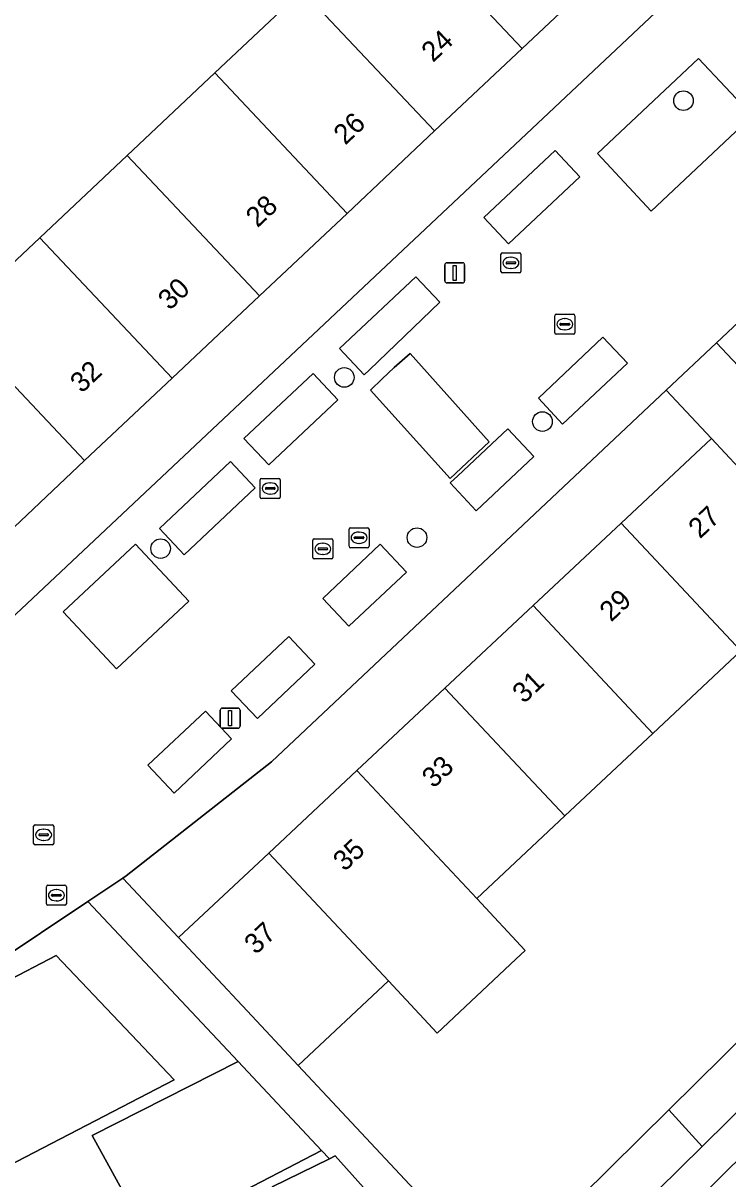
# Model space of a CAD drawing. Extents: x 161881 to 162523, y 381678 to 382381.
# Drawn here: x 162341.8 to 162377, y 381766.4 to 381824.1 of the extents above; entities that cross this region are included whole.
import ezdxf

# ---------------------------------------------------------------- set-up
doc = ezdxf.new("R2010")
doc.units = 0
for name, color, linetype in [('IMGEO_Boom', 7, 'Continuous'), ('IMGEO_Brandkraan', 7, 'Continuous'), ('IMGEO_Erf', 7, 'Continuous'), ('IMGEO_Groenvoorziening', 7, 'Continuous'), ('IMGEO_Kolk', 7, 'Continuous'), ('IMGEO_Lichtmast', 7, 'Continuous'), ('IMGEO_Pand', 7, 'Continuous'), ('IMGEO_Pand_nummerreeks', 7, 'Continuous'), ('IMGEO_Parkeervlak_open', 7, 'Continuous'), ('IMGEO_Rijbaan_lokaal_open', 7, 'Continuous'), ('IMGEO_Rioolput', 7, 'Continuous'), ('IMGEO_Voetpad_open', 7, 'Continuous')]:
    doc.layers.add(name, color=color, linetype=linetype)

msp = doc.modelspace()

# ---------------------------------------------------------------- linework, layer by layer
at = {"layer": 'IMGEO_Boom'}
for centre in [(162374.75, 381820.189), (162357.829, 381806.387), (162367.715, 381804.185), (162361.458, 381798.398), (162348.668, 381797.849)]:
    msp.add_circle(centre, 0.489, dxfattribs=at)
at = {"layer": 'IMGEO_Brandkraan'}
for p, q in [((162342.967, 381780.137), (162342.967, 381780.989)), ((162343.042, 381781.063), (162343.894, 381781.063)), ((162343.455, 381780.843), (162343.48, 381780.843)), ((162343.968, 381780.989), (162343.968, 381780.137)), ((162343.226, 381780.557), (162343.226, 381780.569)), ((162343.664, 381780.52), (162343.266, 381780.52)), ((162343.269, 381780.606), (162343.667, 381780.606)), ((162343.478, 381780.283), (162343.453, 381780.283)), ((162343.71, 381780.569), (162343.71, 381780.557)), ((162343.894, 381780.063), (162343.042, 381780.063))]:
    msp.add_line(p, q, dxfattribs=at)
for points in [[(162342.967, 381780.137), (162342.967, 381780.989)], [(162343.042, 381781.063), (162343.894, 381781.063)], [(162343.968, 381780.989), (162343.968, 381780.137)], [(162343.894, 381780.063), (162343.042, 381780.063)]]:
    msp.add_lwpolyline(points, dxfattribs=at)
for centre, radius, start, end in [((162343.044, 381780.987), 0.0765, 91.55205, 178.44795), ((162343.044, 381780.987), 0.0765, 91.55205, 178.44795), ((162343.892, 381780.987), 0.0765, 1.55205, 88.44795), ((162343.892, 381780.987), 0.0765, 1.55205, 88.44795), ((162343.266, 381780.566), 0.0403, 85.87752, 175.75265), ((162343.263, 381780.556), 0.0366, 178.93798, 274.71019), ((162343.667, 381780.563), 0.043, 264.86636, 352.45326), ((162343.671, 381780.568), 0.0386, 1.73085, 96.63898), ((162343.044, 381780.139), 0.0765, 181.55205, 268.44795), ((162343.044, 381780.139), 0.0765, 181.55205, 268.44795), ((162343.892, 381780.139), 0.0765, 271.55205, 358.44795), ((162343.892, 381780.139), 0.0765, 271.55205, 358.44795)]:
    msp.add_arc(centre, radius, start, end, dxfattribs=at)
for centre, major_axis, ratio, start_param, end_param in [((162343.454, 381780.563), (-0.387, 0.002), 0.722429, 4.712389, 7.853982), ((162343.479, 381780.563), (-0.39, 0.002), 0.717154, 1.570796, 4.712389)]:
    msp.add_ellipse(centre, major_axis=major_axis, ratio=ratio, start_param=start_param, end_param=end_param, dxfattribs=at)
at = {"layer": 'IMGEO_Erf'}
for points in [[(162414.428, 381843.9), (162376.404, 381808.113), (162383.389, 381800.691)], [(162332.07, 381824.564), (162327.383, 381820.796), (162319.893, 381814.774), (162328.853, 381805.184), (162331.62, 381807.79), (162334.025, 381805.238), (162338.274, 381809.24), (162342.639, 381813.35), (162347.004, 381817.46), (162351.368, 381821.57), (162355.733, 381825.68)], [(162369.629, 381765.527), (162374.022, 381769.859), (162378.082, 381773.863), (162382.473, 381778.193), (162386.785, 381782.445), (162390.429, 381786.038), (162389.849, 381786.627), (162387.914, 381788.589), (162389.897, 381790.545), (162394.14, 381786.241), (162394.352, 381786.45), (162385.347, 381796.033), (162382.932, 381796.092), (162382.12, 381796.96), (162377.619, 381792.746), (162373.224, 381788.631), (162368.83, 381784.517), (162364.435, 381780.403), (162366.852, 381777.807), (162366.391, 381777.376), (162362.458, 381773.692), (162360.041, 381776.288), (162355.536, 381772.071), (162363.995, 381763.033)], [(162354.236, 381766.022), (162357.084, 381767.419), (162356.7, 381767.828), (162348.117, 381763.384), (162345.256, 381768.578), (162352.533, 381772.272), (162345.044, 381780.258), (162340.347, 381777.133), (162340.852, 381776.203), (162343.461, 381777.564), (162346.9, 381773.934), (162349.34, 381771.36), (162327.927, 381760.251)], [(162381.418, 381771.264), (162367.187, 381757.231)]]:
    msp.add_lwpolyline(points, dxfattribs=at)
for points in [[(162377.552, 381828.547), (162383.149, 381833.811), (162380.574, 381836.724), (162378.448, 381836.809), (162374.061, 381832.677), (162375.536, 381831.111), (162371.061, 381826.897), (162366.697, 381822.787), (162362.333, 381818.677), (162357.968, 381814.567), (162353.605, 381810.457), (162349.24, 381806.347), (162344.875, 381802.236), (162340.402, 381798.024), (162340.265, 381798.17), (162339.511, 381798.971), (162336.964, 381796.572), (162337.718, 381795.771), (162340.037, 381793.265)], [(162367.248, 381795.01), (162371.642, 381799.125), (162376.146, 381803.341), (162373.886, 381805.743), (162354.206, 381787.221), (162346.948, 381781.525), (162346.786, 381781.417), (162349.562, 381778.452), (162354.064, 381782.667), (162358.459, 381786.781), (162362.853, 381790.895)]]:
    msp.add_lwpolyline(points, close=True, dxfattribs=at)
at = {"layer": 'IMGEO_Groenvoorziening'}
for points in [[(162373.145, 381814.683), (162378.194, 381819.432), (162375.501, 381822.295), (162370.453, 381817.546)], [(162346.471, 381791.847), (162350.082, 381795.233), (162347.414, 381798.078), (162343.803, 381794.692)]]:
    msp.add_lwpolyline(points, close=True, dxfattribs=at)
at = {"layer": 'IMGEO_Kolk'}
for p, q in [((162365.717, 381812.601), (162366.569, 381812.601)), ((162365.642, 381811.675), (162365.642, 381812.527)), ((162365.901, 381812.095), (162365.901, 381812.107)), ((162366.339, 381812.058), (162365.941, 381812.058)), ((162365.944, 381812.144), (162366.342, 381812.144)), ((162366.13, 381812.381), (162366.155, 381812.381)), ((162366.385, 381812.107), (162366.385, 381812.095)), ((162366.643, 381812.527), (162366.643, 381811.675)), ((162366.569, 381811.601), (162365.717, 381811.601)), ((162366.153, 381811.821), (162366.128, 381811.821)), ((162368.33, 381808.614), (162368.33, 381809.466)), ((162368.405, 381809.54), (162369.257, 381809.54)), ((162368.632, 381809.083), (162369.03, 381809.083)), ((162368.818, 381809.32), (162368.843, 381809.32)), ((162369.331, 381809.466), (162369.331, 381808.614)), ((162369.257, 381808.54), (162368.405, 381808.54)), ((162368.589, 381809.034), (162368.589, 381809.046)), ((162369.027, 381808.997), (162368.629, 381808.997)), ((162368.841, 381808.76), (162368.816, 381808.76)), ((162369.073, 381809.046), (162369.073, 381809.034)), ((162353.635, 381800.423), (162353.635, 381801.275)), ((162353.71, 381801.349), (162354.562, 381801.349)), ((162354.123, 381801.129), (162354.148, 381801.129)), ((162354.636, 381801.275), (162354.636, 381800.423)), ((162353.894, 381800.843), (162353.894, 381800.855)), ((162354.332, 381800.806), (162353.934, 381800.806)), ((162353.937, 381800.892), (162354.335, 381800.892)), ((162354.146, 381800.569), (162354.121, 381800.569)), ((162354.378, 381800.855), (162354.378, 381800.843)), ((162354.562, 381800.349), (162353.71, 381800.349)), ((162356.26, 381797.412), (162356.26, 381798.264)), ((162356.335, 381798.338), (162357.187, 381798.338)), ((162357.261, 381798.264), (162357.261, 381797.412)), ((162356.519, 381797.832), (162356.519, 381797.844)), ((162356.957, 381797.795), (162356.559, 381797.795)), ((162356.562, 381797.881), (162356.96, 381797.881)), ((162356.771, 381797.558), (162356.746, 381797.558)), ((162356.748, 381798.118), (162356.773, 381798.118)), ((162357.003, 381797.844), (162357.003, 381797.832)), ((162357.187, 381797.338), (162356.335, 381797.338)), ((162342.332, 381783.151), (162342.332, 381784.003)), ((162342.407, 381784.077), (162343.259, 381784.077)), ((162342.82, 381783.857), (162342.845, 381783.857)), ((162343.333, 381784.003), (162343.333, 381783.151)), ((162342.591, 381783.571), (162342.591, 381783.583)), ((162343.029, 381783.534), (162342.631, 381783.534)), ((162342.634, 381783.62), (162343.032, 381783.62)), ((162342.843, 381783.297), (162342.818, 381783.297)), ((162343.075, 381783.583), (162343.075, 381783.571)), ((162343.259, 381783.077), (162342.407, 381783.077))]:
    msp.add_line(p, q, dxfattribs=at)
for points in [[(162365.717, 381812.601), (162366.569, 381812.601)], [(162365.642, 381811.675), (162365.642, 381812.527)], [(162366.643, 381812.527), (162366.643, 381811.675)], [(162366.569, 381811.601), (162365.717, 381811.601)], [(162368.33, 381808.614), (162368.33, 381809.466)], [(162368.405, 381809.54), (162369.257, 381809.54)], [(162369.331, 381809.466), (162369.331, 381808.614)], [(162369.257, 381808.54), (162368.405, 381808.54)], [(162353.635, 381800.423), (162353.635, 381801.275)], [(162353.71, 381801.349), (162354.562, 381801.349)], [(162354.636, 381801.275), (162354.636, 381800.423)], [(162354.562, 381800.349), (162353.71, 381800.349)], [(162356.26, 381797.412), (162356.26, 381798.264)], [(162356.335, 381798.338), (162357.187, 381798.338)], [(162357.261, 381798.264), (162357.261, 381797.412)], [(162357.187, 381797.338), (162356.335, 381797.338)], [(162342.332, 381783.151), (162342.332, 381784.003)], [(162342.407, 381784.077), (162343.259, 381784.077)], [(162343.333, 381784.003), (162343.333, 381783.151)], [(162343.259, 381783.077), (162342.407, 381783.077)]]:
    msp.add_lwpolyline(points, dxfattribs=at)
for centre, radius, start, end in [((162365.719, 381812.525), 0.0765, 91.55205, 178.44795), ((162365.719, 381812.525), 0.0765, 91.55205, 178.44795), ((162366.567, 381812.525), 0.0765, 1.55205, 88.44795), ((162366.567, 381812.525), 0.0765, 1.55205, 88.44795), ((162365.941, 381812.104), 0.0403, 85.87752, 175.75265), ((162365.938, 381812.094), 0.0366, 178.93798, 274.71019), ((162366.342, 381812.101), 0.043, 264.86636, 352.45326), ((162366.346, 381812.106), 0.0386, 1.73085, 96.63898), ((162365.719, 381811.677), 0.0765, 181.55205, 268.44795), ((162365.719, 381811.677), 0.0765, 181.55205, 268.44795), ((162366.567, 381811.677), 0.0765, 271.55205, 358.44795), ((162366.567, 381811.677), 0.0765, 271.55205, 358.44795), ((162368.407, 381809.464), 0.0765, 91.55205, 178.44795), ((162368.407, 381809.464), 0.0765, 91.55205, 178.44795), ((162368.629, 381809.043), 0.0403, 85.87752, 175.75265), ((162369.034, 381809.045), 0.0386, 1.73085, 96.63898), ((162369.255, 381809.464), 0.0765, 1.55205, 88.44795), ((162369.255, 381809.464), 0.0765, 1.55205, 88.44795), ((162368.407, 381808.616), 0.0765, 181.55205, 268.44795), ((162368.407, 381808.616), 0.0765, 181.55205, 268.44795), ((162368.626, 381809.033), 0.0366, 178.93798, 274.71019), ((162369.03, 381809.04), 0.043, 264.86636, 352.45326), ((162369.255, 381808.616), 0.0765, 271.55205, 358.44795), ((162369.255, 381808.616), 0.0765, 271.55205, 358.44795), ((162353.712, 381801.273), 0.0765, 91.55205, 178.44795), ((162353.712, 381801.273), 0.0765, 91.55205, 178.44795), ((162354.56, 381801.273), 0.0765, 1.55205, 88.44795), ((162354.56, 381801.273), 0.0765, 1.55205, 88.44795), ((162353.934, 381800.852), 0.0403, 85.87752, 175.75265), ((162353.931, 381800.842), 0.0366, 178.93798, 274.71019), ((162354.335, 381800.849), 0.043, 264.86636, 352.45326), ((162354.339, 381800.854), 0.0386, 1.73085, 96.63898), ((162353.712, 381800.425), 0.0765, 181.55205, 268.44795), ((162353.712, 381800.425), 0.0765, 181.55205, 268.44795), ((162354.56, 381800.425), 0.0765, 271.55205, 358.44795), ((162354.56, 381800.425), 0.0765, 271.55205, 358.44795), ((162356.337, 381798.262), 0.0765, 91.55205, 178.44795), ((162356.337, 381798.262), 0.0765, 91.55205, 178.44795), ((162357.185, 381798.262), 0.0765, 1.55205, 88.44795), ((162357.185, 381798.262), 0.0765, 1.55205, 88.44795), ((162356.559, 381797.841), 0.0403, 85.87752, 175.75265), ((162356.556, 381797.831), 0.0366, 178.93798, 274.71019), ((162356.96, 381797.838), 0.043, 264.86636, 352.45326), ((162356.964, 381797.843), 0.0386, 1.73085, 96.63898), ((162356.337, 381797.414), 0.0765, 181.55205, 268.44795), ((162356.337, 381797.414), 0.0765, 181.55205, 268.44795), ((162357.185, 381797.414), 0.0765, 271.55205, 358.44795), ((162357.185, 381797.414), 0.0765, 271.55205, 358.44795), ((162342.409, 381784.001), 0.0765, 91.55205, 178.44795), ((162342.409, 381784.001), 0.0765, 91.55205, 178.44795), ((162343.257, 381784.001), 0.0765, 1.55205, 88.44795), ((162343.257, 381784.001), 0.0765, 1.55205, 88.44795), ((162342.409, 381783.153), 0.0765, 181.55205, 268.44795), ((162342.409, 381783.153), 0.0765, 181.55205, 268.44795), ((162342.631, 381783.58), 0.0403, 85.87752, 175.75265), ((162342.628, 381783.57), 0.0366, 178.93798, 274.71019), ((162343.032, 381783.577), 0.043, 264.86636, 352.45326), ((162343.036, 381783.582), 0.0386, 1.73085, 96.63898), ((162343.257, 381783.153), 0.0765, 271.55205, 358.44795), ((162343.257, 381783.153), 0.0765, 271.55205, 358.44795)]:
    msp.add_arc(centre, radius, start, end, dxfattribs=at)
for centre, major_axis, ratio, start_param, end_param in [((162366.129, 381812.101), (-0.387, 0.002), 0.722429, 4.712389, 7.853982), ((162366.154, 381812.101), (-0.39, 0.002), 0.717154, 1.570796, 4.712389), ((162368.817, 381809.04), (-0.387, 0.002), 0.722429, 4.712389, 7.853982), ((162368.842, 381809.04), (-0.39, 0.002), 0.717154, 1.570796, 4.712389), ((162354.122, 381800.849), (-0.387, 0.002), 0.722429, 4.712389, 7.853982), ((162354.147, 381800.849), (-0.39, 0.002), 0.717154, 1.570796, 4.712389), ((162356.747, 381797.838), (-0.387, 0.002), 0.722429, 4.712389, 7.853982), ((162356.772, 381797.838), (-0.39, 0.002), 0.717154, 1.570796, 4.712389), ((162342.819, 381783.577), (-0.387, 0.002), 0.722429, 4.712389, 7.853982), ((162342.844, 381783.577), (-0.39, 0.002), 0.717154, 1.570796, 4.712389)]:
    msp.add_ellipse(centre, major_axis=major_axis, ratio=ratio, start_param=start_param, end_param=end_param, dxfattribs=at)
at = {"layer": 'IMGEO_Lichtmast'}
for p, q in [((162362.844, 381811.201), (162362.844, 381812.001)), ((162362.844, 381812.001), (162362.844, 381811.201)), ((162362.944, 381812.101), (162363.734, 381812.101)), ((162363.734, 381812.101), (162362.944, 381812.101)), ((162363.834, 381812.001), (162363.834, 381811.201)), ((162363.834, 381811.201), (162363.834, 381812.001)), ((162363.734, 381811.101), (162362.944, 381811.101)), ((162362.944, 381811.101), (162363.734, 381811.101)), ((162351.639, 381788.993), (162351.639, 381789.793)), ((162351.639, 381789.793), (162351.639, 381788.993)), ((162351.739, 381789.893), (162352.529, 381789.893)), ((162352.529, 381789.893), (162351.739, 381789.893)), ((162352.629, 381789.793), (162352.629, 381788.993)), ((162352.629, 381788.993), (162352.629, 381789.793)), ((162352.529, 381788.893), (162351.739, 381788.893)), ((162351.739, 381788.893), (162352.529, 381788.893))]:
    msp.add_line(p, q, dxfattribs=at)
for points in [[(162363.264, 381811.976), (162363.414, 381811.976), (162363.414, 381811.226), (162363.264, 381811.226), (162363.264, 381811.976)], [(162352.059, 381789.768), (162352.209, 381789.768), (162352.209, 381789.018), (162352.059, 381789.018), (162352.059, 381789.768)]]:
    msp.add_lwpolyline(points, dxfattribs=at)
for centre, start, end in [((162362.944, 381812.001), 90, 180), ((162362.944, 381812.001), 90, 180), ((162363.734, 381812.001), 0, 90), ((162363.734, 381812.001), 360, 90), ((162362.944, 381811.201), 180, 270), ((162362.944, 381811.201), 180, 270), ((162363.734, 381811.201), 270, 0), ((162363.734, 381811.201), 270, 0), ((162351.739, 381789.793), 90, 180), ((162351.739, 381789.793), 90, 180), ((162352.529, 381789.793), 0, 90), ((162352.529, 381789.793), 360, 90), ((162351.739, 381788.993), 180, 270), ((162351.739, 381788.993), 180, 270), ((162352.529, 381788.993), 270, 0), ((162352.529, 381788.993), 270, 0)]:
    msp.add_arc(centre, 0.1, start, end, dxfattribs=at)
at = {"layer": 'IMGEO_Pand'}
for points in [[(162364.461, 381833.9), (162360.097, 381829.79), (162366.697, 381822.787), (162371.061, 381826.897)], [(162362.333, 381818.677), (162366.697, 381822.787), (162360.097, 381829.79), (162355.733, 381825.68)], [(162362.333, 381818.677), (162355.733, 381825.68), (162351.368, 381821.57), (162357.968, 381814.567)], [(162347.004, 381817.46), (162353.605, 381810.457), (162357.968, 381814.567), (162351.368, 381821.57)], [(162342.639, 381813.35), (162349.24, 381806.347), (162353.605, 381810.457), (162347.004, 381817.46)], [(162342.639, 381813.35), (162338.274, 381809.24), (162344.875, 381802.236), (162349.24, 381806.347)], [(162344.875, 381802.236), (162338.274, 381809.24), (162334.025, 381805.238), (162331.62, 381807.79), (162328.853, 381805.184), (162336.964, 381796.572), (162339.511, 381798.971), (162340.265, 381798.17), (162340.402, 381798.024)], [(162377.619, 381792.746), (162382.12, 381796.96), (162379.564, 381799.691), (162376.146, 381803.341), (162371.642, 381799.125)], [(162373.224, 381788.631), (162377.619, 381792.746), (162371.642, 381799.125), (162367.248, 381795.01)], [(162368.83, 381784.517), (162373.224, 381788.631), (162367.248, 381795.01), (162362.853, 381790.895)], [(162368.83, 381784.517), (162362.853, 381790.895), (162358.459, 381786.781), (162364.435, 381780.403)], [(162358.459, 381786.781), (162354.064, 381782.667), (162360.041, 381776.288), (162362.458, 381773.692), (162366.391, 381777.376), (162366.852, 381777.807), (162364.435, 381780.403)], [(162354.064, 381782.667), (162349.562, 381778.452), (162352.98, 381774.802), (162355.536, 381772.071), (162360.041, 381776.288)], [(162328.391, 381770.833), (162331.08, 381765.587), (162325.904, 381762.866), (162321.926, 381761.495), (162320.12, 381766.798), (162314.63, 381764.141), (162315.372, 381761.969), (162313.697, 381761.36), (162315.359, 381756.62), (162323.025, 381759.138), (162323.187, 381758.657), (162327.927, 381760.251), (162349.34, 381771.36), (162346.9, 381773.934), (162343.461, 381777.564), (162340.852, 381776.203), (162330.364, 381770.731), (162329.914, 381771.585)], [(162375.677, 381768.034), (162379.695, 381771.996), (162378.082, 381773.863), (162374.022, 381769.859)], [(162356.7, 381767.828), (162352.533, 381772.272), (162345.256, 381768.578), (162348.117, 381763.384)], [(162369.629, 381765.527), (162371.265, 381763.684), (162375.677, 381768.034), (162374.022, 381769.859)], [(162360.358, 381764.241), (162357.375, 381767.562), (162357.084, 381767.419), (162354.236, 381766.022), (162356.254, 381762.016), (162357.113, 381760.311), (162361.669, 381762.781)]]:
    msp.add_lwpolyline(points, close=True, dxfattribs=at)
at = {"layer": 'IMGEO_Parkeervlak_open'}
for points in [[(162366.029, 381813.051), (162369.576, 381816.388), (162368.341, 381817.7), (162364.794, 381814.363)], [(162362.593, 381810.142), (162361.399, 381811.411), (162357.852, 381808.073), (162357.587, 381807.824), (162358.821, 381806.512), (162359.086, 381806.762)], [(162370.728, 381808.4), (162367.511, 381805.35), (162368.71, 381804.048), (162371.964, 381807.092)], [(162357.507, 381805.275), (162356.273, 381806.587), (162352.824, 381803.343), (162354.059, 381802.031)], [(162365.456, 381803.33), (162363.49, 381801.479), (162363.11, 381801.123), (162364.415, 381799.735), (162367.286, 381802.437), (162365.981, 381803.824)], [(162349.841, 381797.545), (162353.388, 381800.882), (162352.154, 381802.194), (162348.607, 381798.857)], [(162359.626, 381798.068), (162356.755, 381795.366), (162358.06, 381793.979), (162360.932, 381796.681)], [(162355.062, 381793.467), (162352.19, 381790.765), (162353.495, 381789.378), (162356.367, 381792.08)], [(162350.901, 381789.744), (162348.03, 381787.042), (162349.335, 381785.655), (162352.207, 381788.356)]]:
    msp.add_lwpolyline(points, close=True, dxfattribs=at)
at = {"layer": 'IMGEO_Rijbaan_lokaal_open'}
for points in [[(162373.886, 381805.743), (162376.404, 381808.113), (162414.428, 381843.9), (162415.713, 381845.109), (162445.952, 381873.569), (162445.243, 381874.161), (162440.624, 381869.71), (162437.088, 381873.372), (162436.317, 381872.624), (162433.548, 381875.489), (162434.327, 381876.199), (162435.764, 381877.534), (162437.462, 381879.298)], [(162377.552, 381828.547), (162340.037, 381793.265), (162339.247, 381792.69), (162337.86, 381791.68), (162337.099, 381792.618), (162336.934, 381792.508), (162339.301, 381788.958), (162331.668, 381784.055), (162329.445, 381787.515), (162325.988, 381783.891), (162321.869, 381779.571), (162318.379, 381775.91), (162318.58, 381775.651), (162317.309, 381774.987), (162317.648, 381774.288), (162309.959, 381770.404), (162312.53, 381763.243)], [(162314.63, 381764.141), (162320.12, 381766.798), (162328.391, 381770.833), (162329.914, 381771.585), (162328.21, 381775.141), (162330.328, 381776.306), (162338.389, 381780.741), (162340.347, 381777.133), (162345.044, 381780.258), (162346.786, 381781.417), (162346.948, 381781.525), (162354.206, 381787.221), (162373.886, 381805.743)]]:
    msp.add_lwpolyline(points, dxfattribs=at)
for points in [[(162370.453, 381817.546), (162375.501, 381822.295), (162378.194, 381819.432), (162373.145, 381814.683)], [(162366.029, 381813.051), (162364.794, 381814.363), (162368.341, 381817.7), (162369.576, 381816.388)], [(162357.587, 381807.824), (162357.852, 381808.073), (162361.399, 381811.411), (162362.593, 381810.142), (162359.086, 381806.762), (162358.821, 381806.512)], [(162367.511, 381805.35), (162370.728, 381808.4), (162371.964, 381807.092), (162368.71, 381804.048)], [(162365.063, 381803.181), (162363.117, 381801.342), (162359.143, 381805.758), (162359.721, 381806.32), (162360.315, 381806.876), (162361.113, 381807.587)], [(162365.063, 381803.181), (162361.113, 381807.587), (162360.315, 381806.876), (162359.721, 381806.32), (162359.143, 381805.758), (162363.117, 381801.342)], [(162352.824, 381803.343), (162356.273, 381806.587), (162357.507, 381805.275), (162354.059, 381802.031)], [(162365.456, 381803.33), (162365.981, 381803.824), (162367.286, 381802.437), (162364.415, 381799.735), (162363.11, 381801.123), (162363.49, 381801.479)], [(162349.841, 381797.545), (162348.607, 381798.857), (162352.154, 381802.194), (162353.388, 381800.882)], [(162343.803, 381794.692), (162347.414, 381798.078), (162350.082, 381795.233), (162346.471, 381791.847)], [(162359.626, 381798.068), (162360.932, 381796.681), (162358.06, 381793.979), (162356.755, 381795.366)], [(162355.062, 381793.467), (162356.367, 381792.08), (162353.495, 381789.378), (162352.19, 381790.765)], [(162350.901, 381789.744), (162352.207, 381788.356), (162349.335, 381785.655), (162348.03, 381787.042)]]:
    msp.add_lwpolyline(points, close=True, dxfattribs=at)
at = {"layer": 'IMGEO_Rioolput'}
for p, q in [((162358.065, 381797.965), (162358.065, 381798.817)), ((162358.14, 381798.891), (162358.992, 381798.891)), ((162359.066, 381798.817), (162359.066, 381797.965)), ((162358.324, 381798.385), (162358.324, 381798.397)), ((162358.762, 381798.348), (162358.364, 381798.348)), ((162358.367, 381798.434), (162358.765, 381798.434)), ((162358.553, 381798.671), (162358.578, 381798.671)), ((162358.808, 381798.397), (162358.808, 381798.385)), ((162358.992, 381797.891), (162358.14, 381797.891)), ((162358.576, 381798.111), (162358.551, 381798.111))]:
    msp.add_line(p, q, dxfattribs=at)
for points in [[(162358.065, 381797.965), (162358.065, 381798.817)], [(162358.14, 381798.891), (162358.992, 381798.891)], [(162359.066, 381798.817), (162359.066, 381797.965)], [(162358.992, 381797.891), (162358.14, 381797.891)]]:
    msp.add_lwpolyline(points, dxfattribs=at)
for centre, radius, start, end in [((162358.142, 381798.815), 0.0765, 91.55205, 178.44795), ((162358.142, 381798.815), 0.0765, 91.55205, 178.44795), ((162358.99, 381798.815), 0.0765, 1.55205, 88.44795), ((162358.99, 381798.815), 0.0765, 1.55205, 88.44795), ((162358.364, 381798.394), 0.0403, 85.87752, 175.75265), ((162358.361, 381798.384), 0.0366, 178.93798, 274.71019), ((162358.765, 381798.391), 0.043, 264.86636, 352.45326), ((162358.769, 381798.396), 0.0386, 1.73085, 96.63898), ((162358.142, 381797.967), 0.0765, 181.55205, 268.44795), ((162358.142, 381797.967), 0.0765, 181.55205, 268.44795), ((162358.99, 381797.967), 0.0765, 271.55205, 358.44795), ((162358.99, 381797.967), 0.0765, 271.55205, 358.44795)]:
    msp.add_arc(centre, radius, start, end, dxfattribs=at)
for centre, major_axis, ratio, start_param, end_param in [((162358.552, 381798.391), (-0.387, 0.002), 0.722429, 4.712389, 7.853982), ((162358.577, 381798.391), (-0.39, 0.002), 0.717154, 1.570796, 4.712389)]:
    msp.add_ellipse(centre, major_axis=major_axis, ratio=ratio, start_param=start_param, end_param=end_param, dxfattribs=at)
at = {"layer": 'IMGEO_Voetpad_open'}
for points in [[(162367.187, 381757.231), (162381.418, 381771.264), (162389.981, 381779.647), (162399.042, 381788.517), (162408.087, 381797.371), (162426.783, 381815.673), (162435.772, 381824.472), (162444.862, 381833.372)], [(162383.389, 381800.691), (162376.404, 381808.113), (162373.886, 381805.743), (162376.146, 381803.341), (162379.564, 381799.691)], [(162379.695, 381771.996), (162375.677, 381768.034), (162371.265, 381763.684)]]:
    msp.add_lwpolyline(points, dxfattribs=at)
msp.add_lwpolyline([(162355.536, 381772.071), (162352.98, 381774.802), (162349.562, 381778.452), (162346.786, 381781.417), (162345.044, 381780.258), (162352.533, 381772.272), (162356.7, 381767.828), (162357.084, 381767.419), (162357.375, 381767.562), (162360.358, 381764.241), (162361.669, 381762.781), (162362.713, 381761.769), (162365.972, 381758.464), (162367.003, 381759.48), (162365.275, 381761.233), (162365.51, 381761.465), (162363.995, 381763.033)], close=True, dxfattribs=at)

# ---------------------------------------------------------------- texts
at = {"layer": 'IMGEO_Pand_nummerreeks'}
for s, rotation, p in [('24', 43.28133, (162362.256, 381822.067)), ('26', 43.28133, (162357.876, 381817.942)), ('28', 43.28133, (162353.498, 381813.819)), ('30', 43.28133, (162349.118, 381809.694)), ('32', 43.28133, (162344.734, 381805.565)), ('27', 43.11394, (162375.57, 381798.307)), ('29', 43.11394, (162371.139, 381794.159)), ('31', 43.11394, (162366.79, 381790.089)), ('33', 43.11394, (162362.278, 381785.862)), ('35', 43.11507, (162357.846, 381781.714)), ('37', 43.11394, (162353.416, 381777.566))]:
    msp.add_text(s, height=1, rotation=rotation, dxfattribs=at).set_placement(p)

doc.saveas('drawing.dxf')
